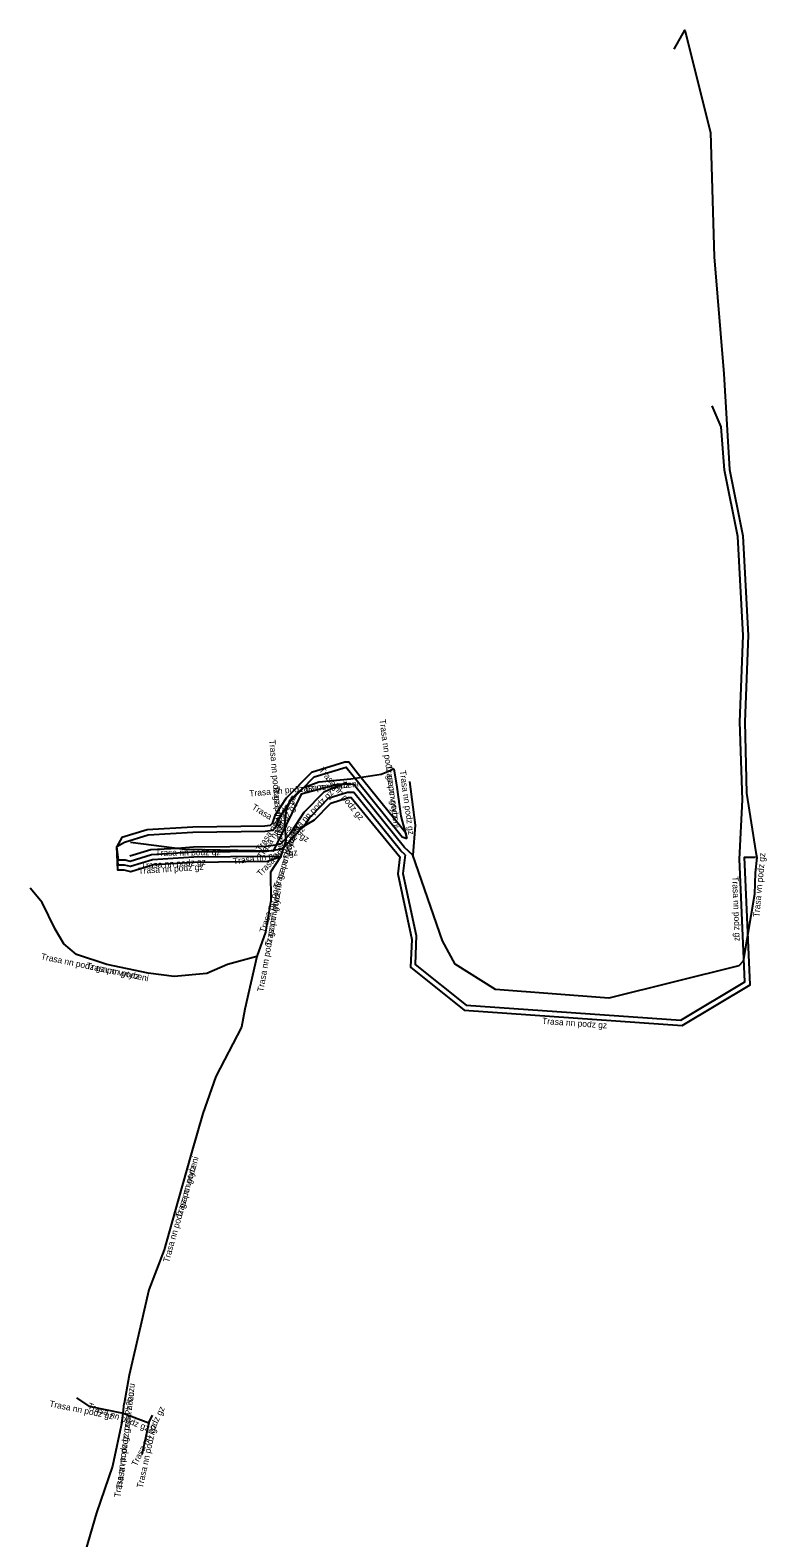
# Model space of a CAD drawing. Extents: x -745976 to -745601, y -957929 to -957686.
# Drawn here: x -745659.5 to -745601, y -957805.7 to -957686 of the extents above; entities that cross this region are included whole.
import ezdxf

# ---------------------------------------------------------------- set-up
doc = ezdxf.new("R2010")
doc.units = 0
for name, color, linetype in [('Popiskový text - Ostatní atributy Trasy', 7, 'Continuous'), ('Spojnice NN', 7, 'Continuous'), ('Spojnice VN', 7, 'Continuous')]:
    doc.layers.add(name, color=color, linetype=linetype)

msp = doc.modelspace()

# ---------------------------------------------------------------- linework, layer by layer
at = {"layer": 'Spojnice NN'}
for points in [[(-745629.73, -957751.47), (-745629.9, -957752.95), (-745628.86, -957757.86), (-745628.93, -957760.17), (-745624.89, -957763.4), (-745607.86, -957764.59), (-745602.79, -957761.55), (-745603.21, -957751.81), (-745602.98, -957747.09), (-745603.19, -957740.9), (-745602.92, -957734.07), (-745603.34, -957726.21), (-745604.4, -957720.93), (-745604.68, -957717.49), (-745605.39, -957715.84)], [(-745629.59, -957750.18), (-745629.64, -957749.77), (-745633.44, -957745.05), (-745634.2, -957744.11), (-745634.5, -957744.11), (-745637.16, -957744.92), (-745639.16, -957746.97), (-745640.06, -957748.35), (-745640.27, -957748.97), (-745640.42, -957749.13), (-745640.86, -957749.19), (-745646.57, -957749.26), (-745650.18, -957749.48), (-745652.2, -957750.1), (-745652.58, -957750.81)], [(-745652.58, -957750.81), (-745651.97, -957750.45), (-745650.11, -957749.88), (-745646.55, -957749.66), (-745640.83, -957749.59), (-745640.23, -957749.5), (-745639.92, -957749.18), (-745639.7, -957748.53), (-745638.85, -957747.22), (-745636.94, -957745.27), (-745634.41, -957744.5), (-745633.63, -957745.46), (-745629.95, -957750.03), (-745629.59, -957750.18)], [(-745630.63, -957744.63), (-745630.98, -957744.83), (-745631.63, -957745.08), (-745634.03, -957745.46), (-745636.58, -957745.69), (-745637.84, -957746.16), (-745638.79, -957747.04), (-745639.15, -957747.88)], [(-745630.63, -957744.63), (-745630.98, -957744.83), (-745631.63, -957745.08), (-745634.03, -957745.46), (-745636.58, -957745.69), (-745637.84, -957746.16), (-745638.79, -957747.04), (-745639.15, -957747.88)], [(-745634.34, -957745.71), (-745636.17, -957746.48), (-745637.75, -957748.1), (-745638.45, -957749.16)], [(-745630.63, -957744.63), (-745630.39, -957746.1), (-745630.08, -957748.39), (-745629.59, -957750.18)], [(-745630.63, -957744.63), (-745630.39, -957746.1), (-745630.08, -957748.39), (-745629.59, -957750.18)], [(-745629.39, -957745.65), (-745628.92, -957749.11), (-745629.13, -957751.49)], [(-745629.73, -957751.47), (-745630.08, -957751.14), (-745633.8, -957746.52), (-745634.29, -957746.51), (-745635.84, -957747), (-745637.13, -957748.33), (-745637.28, -957748.48), (-745637.76, -957749.21), (-745637.97, -957749.37), (-745639.44, -957751.01), (-745640.71, -957751.19), (-745646.48, -957751.26), (-745649.83, -957751.47), (-745651.52, -957751.98), (-745651.92, -957751.89), (-745652.45, -957751.89), (-745652.58, -957750.81)], [(-745638.09, -957749.38), (-745636.92, -957748.68), (-745635.62, -957747.35), (-745634.23, -957746.91), (-745634, -957746.92), (-745630.15, -957751.62)], [(-745639.15, -957747.88), (-745639.3, -957749.02), (-745639.19, -957750.33)], [(-745639.15, -957747.88), (-745639.3, -957749.02), (-745639.19, -957750.33)], [(-745638.45, -957749.16), (-745638.87, -957749.81), (-745639.64, -957750.63)], [(-745638.45, -957749.16), (-745638.09, -957749.38)], [(-745639.19, -957750.33), (-745639.6, -957751.63)], [(-745639.19, -957750.33), (-745639.6, -957751.63)], [(-745639.6, -957751.63), (-745640.65, -957751.99), (-745646.45, -957752.06), (-745649.69, -957752.26), (-745651.49, -957752.81), (-745652.02, -957752.69), (-745652.5, -957752.69), (-745652.58, -957750.81)], [(-745639.6, -957751.63), (-745640.68, -957751.59), (-745646.47, -957751.66), (-745649.76, -957751.86), (-745651.51, -957752.4), (-745651.97, -957752.29), (-745652.47, -957752.29), (-745652.58, -957750.81)], [(-745639.64, -957750.63), (-745640.74, -957750.79), (-745646.5, -957750.86), (-745647.78, -957750.95), (-745649.9, -957751.07), (-745651.56, -957751.58)], [(-745639.6, -957751.63), (-745640.41, -957752.83), (-745640.37, -957755.05), (-745640.81, -957757.6), (-745641.48, -957759.54)], [(-745639.6, -957751.63), (-745640.41, -957752.83), (-745640.37, -957755.05), (-745640.81, -957757.6), (-745641.48, -957759.54)], [(-745630.15, -957751.62), (-745630.3, -957752.97), (-745629.2, -957758.18), (-745629.3, -957760.39), (-745625.04, -957763.8), (-745607.76, -957765), (-745602.38, -957761.77), (-745602.81, -957751.66), (-745601.95, -957751.65)], [(-745641.48, -957759.54), (-745643.82, -957760.17), (-745645.45, -957760.87), (-745648.04, -957761.13), (-745650.1, -957760.85), (-745653.39, -957760.17), (-745655.78, -957759.38), (-745656.8, -957758.52), (-745657.48, -957757.37), (-745658.52, -957755.24), (-745659.46, -957754.11)], [(-745641.48, -957759.54), (-745643.82, -957760.17), (-745645.45, -957760.87), (-745648.04, -957761.13), (-745650.1, -957760.85), (-745653.39, -957760.17), (-745655.78, -957759.38), (-745656.8, -957758.52), (-745657.48, -957757.37), (-745658.52, -957755.24), (-745659.46, -957754.11)], [(-745641.48, -957759.54), (-745642.45, -957763.72), (-745642.71, -957765.14), (-745644.74, -957769.06), (-745645.78, -957771.99), (-745646.66, -957775.1), (-745647.75, -957778.95), (-745648.84, -957782.8), (-745650.05, -957785.98), (-745650.71, -957788.86), (-745651.61, -957792.75), (-745652, -957795.01)], [(-745641.48, -957759.54), (-745642.45, -957763.72), (-745642.71, -957765.14), (-745644.74, -957769.06), (-745645.78, -957771.99), (-745646.66, -957775.1), (-745647.75, -957778.95), (-745648.84, -957782.8), (-745650.05, -957785.98), (-745650.71, -957788.86), (-745651.61, -957792.75), (-745652, -957795.01)], [(-745655.79, -957794.56), (-745654.8, -957795.22), (-745652.09, -957795.77)], [(-745652.17, -957796.38), (-745652.09, -957795.77)], [(-745652.09, -957795.77), (-745652, -957795.01)], [(-745652.09, -957795.77), (-745650.05, -957796.54)], [(-745650.05, -957796.54), (-745649.76, -957795.94)], [(-745652.17, -957796.38), (-745652.93, -957799.97), (-745654.21, -957803.68), (-745655.27, -957807.31), (-745656.25, -957810.89), (-745656.47, -957812.53), (-745656.39, -957814.96), (-745657.14, -957817.94), (-745657.17, -957820.19), (-745656.3, -957822), (-745655.8, -957823.35)], [(-745652.17, -957796.38), (-745652.93, -957799.97), (-745654.21, -957803.68), (-745655.27, -957807.31), (-745656.25, -957810.89), (-745656.47, -957812.53), (-745656.39, -957814.96), (-745657.14, -957817.94), (-745657.17, -957820.19), (-745656.3, -957822), (-745655.8, -957823.35)], [(-745650.05, -957796.54), (-745650.61, -957799.07)]]:
    msp.add_lwpolyline(points, dxfattribs=at)
at = {"layer": 'Spojnice VN'}
msp.add_lwpolyline([(-745608.4, -957687.53), (-745607.56, -957686.02), (-745605.52, -957694.14), (-745605.23, -957704.01), (-745604.45, -957713.3), (-745604, -957720.88), (-745602.94, -957726.16), (-745602.52, -957734.07), (-745602.79, -957740.9), (-745602.65, -957746.58), (-745601.92, -957751.28), (-745601.85, -957751.67), (-745601.96, -957752.88), (-745602.03, -957754.58), (-745602.91, -957759.9), (-745603.27, -957760.27), (-745613.58, -957762.85), (-745622.56, -957762.16), (-745625.76, -957760.15), (-745626.77, -957758.29), (-745629.13, -957751.49), (-745629.78, -957750.87), (-745633.82, -957745.86), (-745635.08, -957745.88), (-745637.96, -957746.64), (-745640.19, -957751.17), (-745647.2, -957751.03), (-745651.5, -957750.49)], dxfattribs=at)

# ---------------------------------------------------------------- texts
at = {"layer": 'Popiskový text - Ostatní atributy Trasy'}
for s, rotation, p in [('Trasa nn podz gz po vytyceni', 277.7093, (-745631.77, -957740.74)), ('Trasa nn podz gz po vytyceni', 274.7998, (-745640.51, -957742.35)), ('Trasa nn podz gz', 309.2616, (-745636.59, -957744.76)), ('Trasa nn podz', 277.7093, (-745631.28, -957744.39)), ('Trasa nn podz gz po vytyceni', 5.1539, (-745642.06, -957746.84)), ('Trasa nn podz', 5.1539, (-745638.39, -957746.51)), ('Trasa nn podz gz', 277.7356, (-745630.16, -957744.79)), ('Trasa nn podz gz', 56.8304, (-745641.18, -957751.24)), ('Trasa nn podz', 274.7998, (-745640.2, -957746.02)), ('Trasa nn podz gz', 45.7162, (-745638.96, -957750.28)), ('Trasa nn podz gz', 328.7531, (-745641.93, -957747.81)), ('Trasa nn podz gz', 56.799, (-745641.08, -957751.82)), ('Trasa nn podz gz', 46.8012, (-745641.18, -957753.22)), ('Trasa nn podz gz po vytyceni', 72.5523, (-745640.82, -957757.69)), ('Trasa nn podz', 72.5523, (-745639.72, -957754.18)), ('Trasa nn podz gz', 0.6963, (-745649.52, -957751.55)), ('Trasa nn podz gz', 8.2759, (-745643.34, -957752.23)), ('Trasa vn podz gz', 84.6471, (-745601.64, -957756.43)), ('Trasa nn podz gz', 3.5543, (-745650.86, -957752.98)), ('Trasa nn podz gz', 3.5297, (-745650.67, -957752.57)), ('Trasa nn podz gz po vytyceni', 80.2101, (-745640.97, -957762.37)), ('Trasa nn podz gz', 272.4581, (-745603.8, -957753.18)), ('Trasa nn podz', 80.2101, (-745640.35, -957758.74)), ('Trasa nn podz gz po vytyceni', 348.3221, (-745658.64, -957759.75)), ('Trasa nn podz', 348.3221, (-745655.03, -957760.49)), ('Trasa nn podz gz', 356.0086, (-745618.88, -957764.88)), ('Trasa nn podz gz po vytyceni', 74.1923, (-745648.46, -957783.85)), ('Trasa nn podz', 74.1923, (-745647.46, -957780.3)), ('Trasa nn podz gz po z?hozu', 83.2464, (-745652.15, -957801.8)), ('Trasa nn podz gz', 348.5275, (-745657.97, -957795.24)), ('Trasa nn podz gz po z?hozu', 82.5284, (-745652.31, -957802.48)), ('Trasa nn podz gz', 339.3209, (-745654.94, -957795.39)), ('Trasa nn podz gz', 64.204, (-745651.01, -957800.03)), ('Trasa nn podz gz', 77.5192, (-745650.54, -957801.75))]:
    msp.add_text(s, height=0.5, rotation=rotation, dxfattribs=at).set_placement(p)

doc.saveas('drawing.dxf')
